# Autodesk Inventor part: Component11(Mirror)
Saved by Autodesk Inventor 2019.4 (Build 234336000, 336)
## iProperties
Created: 2020-06
Part Number: Component11(Mirror)
Material: Generic
Document SubType Name: Modeling
Designer: Administrator
Density: 1 g/cm^3
Appearance: Default
Title: Component11(Mirror)
Author: Administrator
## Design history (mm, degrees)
